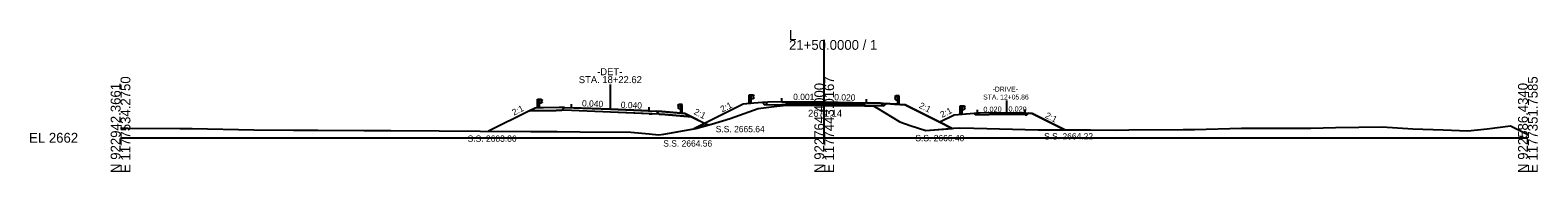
# Model space of a CAD drawing. Extents: x -26 to 1403, y -10 to 9563.
# Drawn here: x 974.3 to 1402.8, y 1490.3 to 1530.6 of the extents above; entities that cross this region are included whole.
import ezdxf

# ---------------------------------------------------------------- set-up
doc = ezdxf.new("R2010")
doc.units = 0
for name, color, linetype in [('Exist Cross Section Cell', 7, 'Continuous'), ('Exist XS Center Line Elevation Label', 7, 'Continuous'), ('Exist XS Ground Line', 7, 'Continuous'), ('Prop XS Ditch Slope Text', 7, 'Continuous'), ('Prop XS Dump Level', 7, 'Continuous'), ('Prop XS Earthwork Shape', 7, 'Continuous'), ('Prop XS EOT Tick Mark', 7, 'Continuous'), ('Prop XS Finish Grade', 7, 'Continuous'), ('Prop XS Finish Grade Earthwork', 7, 'Continuous'), ('Prop XS Finish Grade Paved Shoulder', 7, 'Continuous'), ('Prop XS Finish Grade Pavement', 7, 'Continuous'), ('Prop XS Guardrail', 7, 'Continuous'), ('Prop XS Pvmt Edge Slope', 7, 'Continuous'), ('Prop XS SE Text', 7, 'Continuous'), ('Prop XS Shoulder Borrow Shape', 7, 'Continuous'), ('Prop XS Side Slope Text', 7, 'Continuous'), ('Prop XS SS Elevation Text', 7, 'Continuous'), ('Prop XS Subgrade Earthwork', 7, 'Continuous'), ('Prop XS Vertical Lines', 7, 'Continuous'), ('Prop XS Vertical Lines Alignments', 7, 'Continuous'), ('Prop XS Wedging', 7, 'Continuous')]:
    doc.layers.add(name, color=color, linetype=linetype)

msp = doc.modelspace()

# ---------------------------------------------------------------- linework, layer by layer
at = {"layer": 'Exist Cross Section Cell'}
for p, q in [((1200, 1500), (1200, 1527.82)), ((1000, 1500), (1200, 1500)), ((1200, 1500), (1400, 1500))]:
    msp.add_line(p, q, dxfattribs=at)
at = {"layer": 'Exist XS Ground Line'}
for p, q in [((1181.25, 1508.36), (1186.57, 1508.97)), ((1186.57, 1508.97), (1189.25, 1509.27)), ((1189.25, 1509.27), (1190.39, 1509.26)), ((1190.39, 1509.26), (1199.9, 1509.14)), ((1199.9, 1509.14), (1201.2, 1509.14)), ((1201.2, 1509.14), (1211.45, 1509.13)), ((1211.45, 1509.13), (1214.09, 1508.99)), ((1214.09, 1508.99), (1214.92, 1508.5)), ((1214.92, 1508.5), (1221.5, 1504.55)), ((1167.93, 1503.91), (1173.26, 1505.47)), ((1173.26, 1505.47), (1181.25, 1508.36)), ((1221.5, 1504.55), (1224.42, 1503.48)), ((1000, 1502.7), (1002.04, 1502.7)), ((1002.04, 1502.7), (1016.87, 1502.66)), ((1016.87, 1502.66), (1019.21, 1502.63)), ((1019.21, 1502.63), (1020.39, 1502.62)), ((1020.39, 1502.62), (1037.86, 1502.27)), ((1037.86, 1502.27), (1049.13, 1502.16)), ((1049.13, 1502.16), (1056.03, 1502.13)), ((1056.03, 1502.13), (1069.18, 1502.09)), ((1069.18, 1502.09), (1076.78, 1502.07)), ((1076.78, 1502.07), (1090.56, 1501.99)), ((1090.56, 1501.99), (1102.17, 1501.87)), ((1102.17, 1501.87), (1116.6, 1501.81)), ((1116.6, 1501.81), (1124.1, 1501.75)), ((1124.1, 1501.75), (1130.67, 1501.7)), ((1130.67, 1501.7), (1145.06, 1501.56)), ((1145.06, 1501.56), (1150.28, 1501.09)), ((1150.28, 1501.09), (1151.13, 1501.01)), ((1151.13, 1501.01), (1153.02, 1500.84)), ((1153.02, 1500.84), (1154.42, 1501.07)), ((1154.42, 1501.07), (1163.49, 1502.66)), ((1163.49, 1502.66), (1167.93, 1503.91)), ((1224.42, 1503.48), (1228.86, 1502.05)), ((1228.86, 1502.05), (1236.86, 1502.7)), ((1236.86, 1502.7), (1238.5, 1502.85)), ((1238.5, 1502.85), (1242.53, 1502.74)), ((1242.53, 1502.74), (1260.83, 1502.22)), ((1260.83, 1502.22), (1275.68, 1502.22)), ((1275.68, 1502.22), (1282.9, 1502.19)), ((1282.9, 1502.19), (1286.55, 1502.27)), ((1286.55, 1502.27), (1302.06, 1502.32)), ((1302.06, 1502.32), (1305.22, 1502.4)), ((1305.22, 1502.4), (1318.57, 1502.71)), ((1318.57, 1502.71), (1336.88, 1502.76)), ((1336.88, 1502.76), (1338.36, 1502.75)), ((1338.36, 1502.75), (1345.36, 1502.89)), ((1345.36, 1502.89), (1358.59, 1503.1)), ((1358.59, 1503.1), (1367.27, 1502.58)), ((1367.27, 1502.58), (1375.97, 1502.26)), ((1375.97, 1502.26), (1382.92, 1501.95)), ((1382.92, 1501.95), (1388.43, 1502.53)), ((1388.43, 1502.53), (1395.11, 1503.36)), ((1395.11, 1503.36), (1400, 1500.96))]:
    msp.add_line(p, q, dxfattribs=at)
at = {"layer": 'Prop XS Dump Level'}
for p, q in [((1126.22, 1508.64), (1139.23, 1508.11)), ((1139.23, 1508.11), (1128.21, 1508.56)), ((1188, 1510.23), (1200, 1510.22)), ((1200, 1510.22), (1212, 1509.98)), ((1150.25, 1507.67), (1139.23, 1508.11)), ((1139.23, 1508.11), (1152.25, 1507.59)), ((1244.26, 1506.99), (1243.57, 1506.97)), ((1251.9, 1507.14), (1257.09, 1507.04)), ((1257.09, 1507.04), (1251.9, 1507.14))]:
    msp.add_line(p, q, dxfattribs=at)
at = {"layer": 'Prop XS Earthwork Shape'}
for p, q in [((1177, 1509.59), (1166.02, 1504.11)), ((1178.68, 1509.73), (1177, 1509.59)), ((1182.43, 1510.03), (1180, 1509.83)), ((1181.25, 1508.36), (1186.57, 1508.97)), ((1183.15, 1509.3), (1182.43, 1510.03)), ((1188, 1509.4), (1183.15, 1509.3)), ((1186.57, 1508.97), (1189.25, 1509.27)), ((1189.25, 1509.4), (1188, 1509.4)), ((1189.25, 1509.27), (1189.25, 1509.4)), ((1216.85, 1509.05), (1211.45, 1509.16)), ((1211.45, 1509.16), (1211.45, 1509.13)), ((1211.45, 1509.13), (1214.09, 1508.99)), ((1214.09, 1508.99), (1214.92, 1508.5)), ((1214.92, 1508.5), (1221.5, 1504.55)), ((1217.57, 1509.78), (1216.85, 1509.05)), ((1220, 1509.58), (1217.57, 1509.78)), ((1220.82, 1509.52), (1220, 1509.58)), ((1232.88, 1504.4), (1223, 1509.34)), ((1116.19, 1507.65), (1104.61, 1501.86)), ((1123.84, 1507.8), (1116.19, 1507.65)), ((1125.41, 1507.83), (1123.84, 1507.8)), ((1128.21, 1507.72), (1125.41, 1507.83)), ((1139.23, 1507.28), (1128.21, 1507.72)), ((1154.72, 1506.59), (1153.11, 1506.72)), ((1162.25, 1505.99), (1154.72, 1506.59)), ((1166.02, 1504.11), (1162.25, 1505.99)), ((1167.93, 1503.91), (1173.26, 1505.47)), ((1173.26, 1505.47), (1181.25, 1508.36)), ((1221.5, 1504.55), (1224.42, 1503.48)), ((1236.97, 1506.45), (1232.88, 1504.4)), ((1232.88, 1504.4), (1236.36, 1502.66)), ((1236.36, 1502.66), (1232.88, 1504.4)), ((1243.06, 1506.46), (1242.62, 1506.9)), ((1246.9, 1506.54), (1243.06, 1506.46)), ((1251.9, 1506.64), (1246.9, 1506.54)), ((1257.09, 1506.54), (1251.9, 1506.64)), ((1257.6, 1506.53), (1257.09, 1506.54)), ((1258.03, 1506.96), (1257.6, 1506.53)), ((1259.09, 1506.88), (1258.03, 1506.96)), ((1268.41, 1502.22), (1259.09, 1506.88)), ((1104.61, 1501.86), (1116.6, 1501.81)), ((1116.6, 1501.81), (1124.1, 1501.75)), ((1124.1, 1501.75), (1130.67, 1501.7)), ((1130.67, 1501.7), (1145.06, 1501.56)), ((1145.06, 1501.56), (1150.28, 1501.09)), ((1150.28, 1501.09), (1151.13, 1501.01)), ((1151.13, 1501.01), (1153.02, 1500.84)), ((1153.02, 1500.84), (1154.42, 1501.07)), ((1154.42, 1501.07), (1162.94, 1502.56)), ((1162.94, 1502.56), (1166.02, 1504.11)), ((1166.02, 1504.11), (1162.94, 1502.56)), ((1166.02, 1504.11), (1162.94, 1502.56)), ((1162.94, 1502.56), (1163.49, 1502.66)), ((1162.94, 1502.56), (1163.49, 1502.66)), ((1163.49, 1502.66), (1166.96, 1503.64)), ((1163.49, 1502.66), (1166.96, 1503.64)), ((1166.96, 1503.64), (1166.02, 1504.11)), ((1166.96, 1503.64), (1166.02, 1504.11)), ((1166.02, 1504.11), (1166.96, 1503.64)), ((1166.96, 1503.64), (1167.93, 1503.91)), ((1224.42, 1503.48), (1228.86, 1502.05)), ((1228.86, 1502.05), (1236.36, 1502.66)), ((1236.36, 1502.66), (1236.86, 1502.7)), ((1236.86, 1502.7), (1238.5, 1502.85)), ((1238.5, 1502.85), (1242.53, 1502.74)), ((1242.53, 1502.74), (1260.83, 1502.22)), ((1260.83, 1502.22), (1268.41, 1502.22))]:
    msp.add_line(p, q, dxfattribs=at)
for points in [[(1180, 1509.83), (1179.18, 1509.77), (1178.68, 1509.73)], [(1223, 1509.34), (1221.32, 1509.48), (1220.82, 1509.52)], [(1153.11, 1506.72), (1151.12, 1506.8), (1150.25, 1506.84), (1139.23, 1507.28)], [(1242.62, 1506.9), (1239.15, 1506.62), (1236.97, 1506.45)]]:
    msp.add_lwpolyline(points, dxfattribs=at)
at = {"layer": 'Prop XS EOT Tick Mark'}
for p, q in [((1128.21, 1508.56), (1128.21, 1509.56)), ((1150.25, 1507.67), (1150.25, 1508.67)), ((1188, 1510.23), (1188, 1511.23)), ((1212, 1509.98), (1212, 1510.98)), ((1243.57, 1506.97), (1243.57, 1507.97)), ((1257.09, 1507.04), (1257.09, 1508.04))]:
    msp.add_line(p, q, dxfattribs=at)
at = {"layer": 'Prop XS Finish Grade'}
for p, q in [((1126.22, 1508.64), (1124.64, 1508.6)), ((1184, 1510.15), (1182.43, 1510.03)), ((1216, 1509.9), (1217.57, 1509.78)), ((1152.25, 1507.59), (1153.85, 1507.46)), ((1243.57, 1506.97), (1242.62, 1506.9)), ((1257.09, 1507.04), (1258.03, 1506.96))]:
    msp.add_line(p, q, dxfattribs=at)
at = {"layer": 'Prop XS Finish Grade Earthwork'}
for p, q in [((1117.82, 1508.47), (1116.19, 1507.65)), ((1120.22, 1508.52), (1117.82, 1508.47)), ((1124.64, 1508.6), (1120.22, 1508.52)), ((1177, 1509.59), (1162.94, 1502.56)), ((1180, 1509.83), (1177, 1509.59)), ((1182.43, 1510.03), (1180, 1509.83)), ((1217.57, 1509.78), (1220, 1509.58)), ((1220, 1509.58), (1223, 1509.34)), ((1223, 1509.34), (1232.88, 1504.4)), ((1116.19, 1507.65), (1104.61, 1501.86)), ((1153.85, 1507.46), (1158.25, 1507.11)), ((1158.25, 1507.11), (1160.35, 1506.94)), ((1160.35, 1506.94), (1162.25, 1505.99)), ((1162.25, 1505.99), (1166.96, 1503.64)), ((1236.97, 1506.45), (1232.88, 1504.4)), ((1242.62, 1506.9), (1236.97, 1506.45)), ((1258.03, 1506.96), (1259.09, 1506.88)), ((1259.09, 1506.88), (1268.41, 1502.22))]:
    msp.add_line(p, q, dxfattribs=at)
at = {"layer": 'Prop XS Finish Grade Paved Shoulder'}
for p, q in [((1188, 1510.23), (1184, 1510.15)), ((1212, 1509.98), (1216, 1509.9))]:
    msp.add_line(p, q, dxfattribs=at)
at = {"layer": 'Prop XS Finish Grade Pavement'}
for p, q in [((1126.22, 1508.64), (1139.23, 1508.11)), ((1188, 1510.23), (1200, 1510.22)), ((1200, 1510.22), (1212, 1509.98)), ((1139.23, 1508.11), (1152.25, 1507.59)), ((1251.9, 1507.14), (1243.57, 1506.97)), ((1251.9, 1507.14), (1257.09, 1507.04))]:
    msp.add_line(p, q, dxfattribs=at)
at = {"layer": 'Prop XS Guardrail'}
for p, q in [((1118.5, 1510.98), (1119, 1510.98)), ((1118.5, 1508.48), (1118.5, 1510.98)), ((1119, 1510.98), (1119.5, 1510.98)), ((1119, 1510.98), (1119, 1508.48)), ((1119.5, 1509.85), (1119, 1509.85)), ((1119.5, 1510.98), (1119.79, 1510.78)), ((1119.79, 1510.66), (1119.5, 1510.46)), ((1119.5, 1510.46), (1119.5, 1510.37)), ((1119.5, 1510.37), (1119.79, 1510.17)), ((1119.79, 1510.05), (1119.5, 1509.85)), ((1119.79, 1510.78), (1119.82, 1510.72)), ((1119.82, 1510.72), (1119.79, 1510.66)), ((1119.79, 1510.17), (1119.82, 1510.11)), ((1119.82, 1510.11), (1119.79, 1510.05)), ((1158.37, 1509.3), (1158.34, 1509.24)), ((1158.34, 1509.24), (1158.37, 1509.18)), ((1158.37, 1508.68), (1158.34, 1508.62)), ((1158.34, 1508.62), (1158.37, 1508.56)), ((1158.66, 1509.5), (1158.37, 1509.3)), ((1158.37, 1509.18), (1158.66, 1508.98)), ((1158.66, 1508.88), (1158.37, 1508.68)), ((1158.37, 1508.56), (1158.66, 1508.36)), ((1159.16, 1509.5), (1158.66, 1509.5)), ((1158.66, 1508.98), (1158.66, 1508.88)), ((1159.66, 1509.5), (1159.16, 1509.5)), ((1159.16, 1509.5), (1159.16, 1507)), ((1159.66, 1507), (1159.66, 1509.5)), ((1178.68, 1512.23), (1179.18, 1512.23)), ((1178.68, 1509.73), (1178.68, 1512.23)), ((1179.18, 1512.23), (1179.68, 1512.23)), ((1179.18, 1512.23), (1179.18, 1509.73)), ((1179.68, 1511.09), (1179.18, 1511.09)), ((1179.68, 1512.23), (1179.97, 1512.03)), ((1179.97, 1511.91), (1179.68, 1511.71)), ((1179.68, 1511.71), (1179.68, 1511.61)), ((1179.68, 1511.61), (1179.97, 1511.41)), ((1179.97, 1511.29), (1179.68, 1511.09)), ((1179.97, 1512.03), (1180, 1511.97)), ((1180, 1511.97), (1179.97, 1511.91)), ((1179.97, 1511.41), (1180, 1511.35)), ((1180, 1511.35), (1179.97, 1511.29)), ((1220.03, 1511.78), (1220, 1511.72)), ((1220, 1511.72), (1220.03, 1511.66)), ((1220.03, 1511.16), (1220, 1511.1)), ((1220, 1511.1), (1220.03, 1511.04)), ((1220.32, 1511.98), (1220.03, 1511.78)), ((1220.03, 1511.66), (1220.32, 1511.46)), ((1220.32, 1511.36), (1220.03, 1511.16)), ((1220.03, 1511.04), (1220.32, 1510.84)), ((1220.82, 1511.98), (1220.32, 1511.98)), ((1220.32, 1511.46), (1220.32, 1511.36)), ((1220.32, 1510.84), (1220.82, 1510.84)), ((1221.32, 1511.98), (1220.82, 1511.98)), ((1220.82, 1511.98), (1220.82, 1509.48)), ((1221.32, 1509.48), (1221.32, 1511.98)), ((1238.65, 1509.12), (1239.15, 1509.12)), ((1238.65, 1506.62), (1238.65, 1509.12)), ((1239.15, 1509.12), (1239.65, 1509.12)), ((1239.15, 1509.12), (1239.15, 1506.62)), ((1239.65, 1509.12), (1239.94, 1508.92)), ((1239.94, 1508.8), (1239.65, 1508.6)), ((1239.65, 1508.6), (1239.65, 1508.51)), ((1239.65, 1508.51), (1239.94, 1508.31)), ((1239.94, 1508.92), (1239.97, 1508.86)), ((1239.97, 1508.86), (1239.94, 1508.8)), ((1158.66, 1508.36), (1159.16, 1508.36)), ((1239.65, 1507.99), (1239.15, 1507.99)), ((1239.94, 1508.19), (1239.65, 1507.99)), ((1239.94, 1508.31), (1239.97, 1508.25)), ((1239.97, 1508.25), (1239.94, 1508.19))]:
    msp.add_line(p, q, dxfattribs=at)
at = {"layer": 'Prop XS Pvmt Edge Slope'}
for p, q in [((1126.22, 1508.64), (1125.41, 1507.83)), ((1184, 1510.15), (1183.15, 1509.3)), ((1216, 1509.9), (1216.85, 1509.05)), ((1152.25, 1507.59), (1153.11, 1506.72)), ((1243.57, 1506.97), (1243.06, 1506.46)), ((1257.09, 1507.04), (1257.6, 1506.53))]:
    msp.add_line(p, q, dxfattribs=at)
at = {"layer": 'Prop XS Shoulder Borrow Shape'}
for p, q in [((1117.82, 1508.47), (1116.19, 1507.65)), ((1118.5, 1508.48), (1117.82, 1508.47)), ((1124.64, 1508.6), (1120.22, 1508.52)), ((1126.22, 1508.64), (1124.64, 1508.6)), ((1125.41, 1507.83), (1126.22, 1508.64)), ((1116.19, 1507.65), (1123.84, 1507.8)), ((1123.84, 1507.8), (1125.41, 1507.83)), ((1153.85, 1507.46), (1152.25, 1507.59)), ((1152.25, 1507.59), (1153.11, 1506.72)), ((1153.11, 1506.72), (1154.72, 1506.59)), ((1158.25, 1507.11), (1153.85, 1507.46)), ((1154.72, 1506.59), (1162.25, 1505.99)), ((1159.16, 1507.04), (1158.25, 1507.11)), ((1162.25, 1505.99), (1160.35, 1506.94))]:
    msp.add_line(p, q, dxfattribs=at)
for points in [[(1120.22, 1508.52), (1119, 1508.49), (1118.5, 1508.48)], [(1160.35, 1506.94), (1159.66, 1507), (1159.16, 1507.04)]]:
    msp.add_lwpolyline(points, dxfattribs=at)
at = {"layer": 'Prop XS Subgrade Earthwork'}
for p, q in [((1183.15, 1509.3), (1182.43, 1510.03)), ((1188, 1509.4), (1183.15, 1509.3)), ((1188, 1509.4), (1189.25, 1509.4)), ((1189.25, 1509.4), (1189.25, 1509.27)), ((1211.45, 1509.16), (1211.45, 1509.11)), ((1211.45, 1509.16), (1216.85, 1509.05)), ((1216.85, 1509.05), (1217.57, 1509.78)), ((1123.84, 1507.8), (1116.19, 1507.65)), ((1125.41, 1507.83), (1123.84, 1507.8)), ((1128.21, 1507.72), (1125.41, 1507.83)), ((1139.23, 1507.28), (1128.21, 1507.72)), ((1153.11, 1506.72), (1139.23, 1507.28)), ((1150.25, 1506.84), (1151.12, 1506.8)), ((1153.11, 1506.72), (1154.72, 1506.59)), ((1154.72, 1506.59), (1162.25, 1505.99)), ((1243.06, 1506.46), (1242.62, 1506.9)), ((1246.9, 1506.54), (1243.06, 1506.46)), ((1251.9, 1506.64), (1246.9, 1506.54)), ((1257.09, 1506.54), (1251.9, 1506.64)), ((1257.09, 1506.54), (1257.6, 1506.53)), ((1257.6, 1506.53), (1258.03, 1506.96))]:
    msp.add_line(p, q, dxfattribs=at)
at = {"layer": 'Prop XS Vertical Lines'}
for p, q in [((1139.23, 1508.11), (1139.23, 1515.11)), ((1251.9, 1507.14), (1251.9, 1510.64))]:
    msp.add_line(p, q, dxfattribs=at)
at = {"layer": 'Prop XS Wedging'}
for points in [[(1189.25, 1509.27), (1189.25, 1509.98), (1190.39, 1509.98), (1199.9, 1509.97), (1200, 1509.97), (1201.2, 1509.95), (1211.45, 1509.74), (1211.45, 1509.13), (1201.2, 1509.14), (1200, 1509.14), (1199.9, 1509.14), (1190.39, 1509.26)], [(1189.25, 1509.27), (1189.25, 1509.98), (1190.39, 1509.98), (1199.9, 1509.97), (1200, 1509.97), (1201.2, 1509.95), (1211.45, 1509.74), (1211.45, 1509.13), (1201.2, 1509.14), (1200, 1509.14), (1199.9, 1509.14), (1190.39, 1509.26)], [(1189.25, 1509.27), (1189.25, 1509.73), (1190.39, 1509.73), (1199.9, 1509.72), (1200, 1509.72), (1201.2, 1509.7), (1211.45, 1509.49), (1211.45, 1509.13), (1201.2, 1509.14), (1200, 1509.14), (1199.9, 1509.14), (1190.39, 1509.26)]]:
    msp.add_lwpolyline(points, close=True, dxfattribs=at)

# ---------------------------------------------------------------- texts
at = {"layer": 'Exist Cross Section Cell'}
for s, p in [('L', (1190, 1527.82)), ('21+50.0000 / 1', (1190, 1525.02)), ('EL 2662', (974, 1498.6))]:
    msp.add_text(s, height=2.8, dxfattribs=at).set_placement(p)
for s, p in [('E 1177534.2750', (1002.8, 1490)), ('E 1177443.0167', (1202.8, 1490)), ('E 1177351.7585', (1402.8, 1490)), ('N 922942.3661', (1000, 1490)), ('N 922764.4000', (1200, 1490)), ('N 922586.4340', (1400, 1490))]:
    msp.add_text(s, height=2.8, rotation=90, dxfattribs=at).set_placement(p)
at = {"layer": 'Exist XS Center Line Elevation Label'}
msp.add_text('2671.14', height=2, dxfattribs=at).set_placement((1195.41, 1505.97))
at = {"layer": 'Prop XS Ditch Slope Text'}
msp.add_text('2:1', height=1.8, rotation=332.6802, dxfattribs=at).set_placement((1162.78, 1506.83))
at = {"layer": 'Prop XS Dump Level'}
for s, p in [('Case2', (1180, 1509.79)), ('Case2', (1220, 1509.54)), ('Case1', (1120.21, 1508.36)), ('Case1', (1158.25, 1506.99)), ('Case1', (1244.9, 1506.84)), ('Case1', (1259.09, 1506.84)), ('Case1', (1261.5, 1505.79))]:
    msp.add_text(s, height=0.04, dxfattribs=at).set_placement(p)
at = {"layer": 'Prop XS SE Text'}
for s, height, rotation, p in [('0.040', 1.8, 357.7035, (1131.13, 1508.94)), ('0.040', 1.8, 357.7033, (1142.15, 1508.5)), ('0.001', 1.8, 359.9454, (1191.18, 1510.73)), ('0.020', 1.8, 358.8542, (1202.84, 1510.66)), ('0.020', 1.5, 1.1458, (1245.27, 1507.31)), ('0.020', 1.5, 358.8542, (1252.36, 1507.47))]:
    msp.add_text(s, height=height, rotation=rotation, dxfattribs=at).set_placement(p)
at = {"layer": 'Prop XS Side Slope Text'}
for rotation, p in [(26.5651, (1111.81, 1506.27)), (26.5651, (1171.04, 1507.19)), (333.4349, (1226.77, 1508.59)), (26.5651, (1233.52, 1505.65)), (333.4349, (1262.65, 1505.77))]:
    msp.add_text('2:1', height=1.8, rotation=rotation, dxfattribs=at).set_placement(p)
at = {"layer": 'Prop XS SS Elevation Text'}
for s, p in [('S.S. 2663.86', (1098.65, 1498.86)), ('S.S. 2665.64', (1169.17, 1501.58)), ('S.S. 2666.40', (1225.91, 1499.02)), ('S.S. 2664.22', (1262.5, 1499.52)), ('S.S. 2664.56', (1154.25, 1497.49))]:
    msp.add_text(s, height=1.8, dxfattribs=at).set_placement(p)
at = {"layer": 'Prop XS Vertical Lines'}
for s, p in [('STA. 18+22.62', (1130.26, 1515.54)), ('-DET-', (1135.47, 1517.79))]:
    msp.add_text(s, height=2, dxfattribs=at).set_placement(p)
at = {"layer": 'Prop XS Vertical Lines Alignments'}
for s, p in [('-DRIVE-', (1247.87, 1513.14)), ('STA. 12+05.86', (1245.18, 1510.89))]:
    msp.add_text(s, height=1.4, dxfattribs=at).set_placement(p)

doc.saveas('drawing.dxf')
